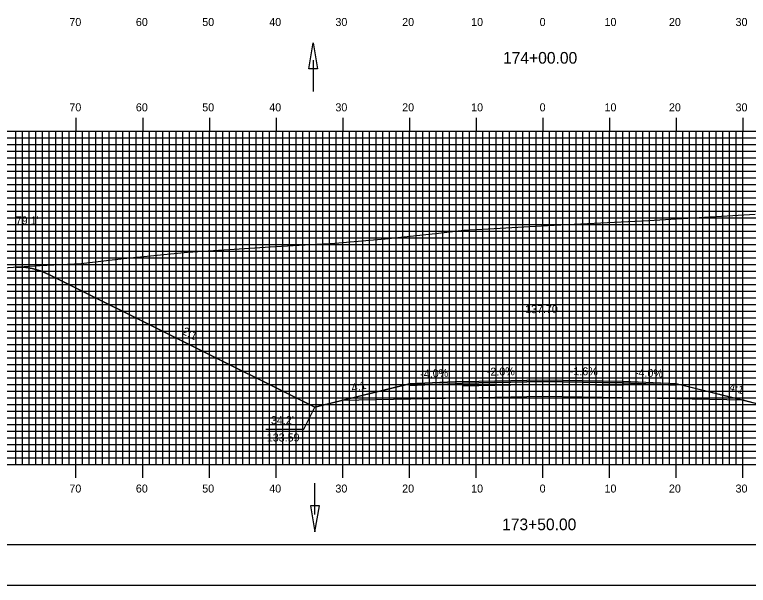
# Model space of a CAD drawing. Extents: x 1783434 to 1783777, y 442591 to 442811.
# Drawn here: x 1783520.8 to 1783630.8, y 442590.5 to 442676.2 of the extents above; entities that cross this region are included whole.
import ezdxf

# ---------------------------------------------------------------- set-up
doc = ezdxf.new("R2010")
doc.units = 0
for name, color, linetype in [('ANNOTATION', 7, 'Continuous'), ('BORDER', 7, 'Continuous'), ('D_Drainage_Ditch_Line', 7, 'Continuous'), ('D_Roadway_Centerline', 7, 'Continuous'), ('D_Roadway_Centerline_Text', 7, 'Continuous'), ('D_Roadway_Edge_Shoulder', 7, 'Continuous'), ('D_Roadway_Edge_TW', 7, 'Continuous'), ('D_Roadway_Pavement', 7, 'Continuous'), ('D_Roadway_SlopeLines', 7, 'Continuous'), ('D_Roadway_SubGrade', 7, 'Continuous'), ('D_Text_Standard', 7, 'Continuous'), ('H_V ANNOTATION', 7, 'Continuous'), ('MAJOR', 7, 'Continuous'), ('MINOR', 7, 'Continuous'), ('PLOT BOUNDARY', 7, 'Continuous'), ('S_Roadway_Centerline', 7, 'Continuous')]:
    doc.layers.add(name, color=color, linetype=linetype)

msp = doc.modelspace()

# ---------------------------------------------------------------- linework, layer by layer
at = {"layer": 'ANNOTATION'}
msp.add_lwpolyline([(1783558.46, 442614), (1783564.15, 442614), (1783565.8, 442617.26)], dxfattribs=at)
at = {"layer": 'BORDER'}
msp.add_lwpolyline([(1783450.37, 442596.67), (1783770.37, 442596.67), (1783770.37, 442806.67), (1783450.37, 442806.67)], close=True, dxfattribs=at)
at = {"layer": 'D_Drainage_Ditch_Line'}
for p, q in [((1783565.54, 442669.34), (1783565.54, 442664.64)), ((1783565.8, 442601.18), (1783565.8, 442605.88))]:
    msp.add_line(p, q, dxfattribs=at)
for points in [[(1783566.2, 442668.03), (1783564.88, 442668.03), (1783565.54, 442671.96)], [(1783566.46, 442602.49), (1783565.14, 442602.49), (1783565.8, 442598.56)]]:
    msp.add_lwpolyline(points, close=True, dxfattribs=at)
at = {"layer": 'D_Roadway_Centerline'}
msp.add_lwpolyline([(1783520.91, 442638.3), (1783522.16, 442638.29), (1783523.41, 442638.1), (1783524.66, 442637.74), (1783525.91, 442637.2), (1783565.8, 442617.26), (1783569.8, 442618.26), (1783579.97, 442620.8), (1783587.97, 442621.12), (1783599.97, 442621.36), (1783611.97, 442621.17), (1783619.97, 442620.85), (1783630.15, 442618.31), (1783636.61, 442616.7), (1783701.63, 442649.21), (1783702.88, 442649.76), (1783704.13, 442650.18), (1783705.38, 442650.47), (1783706.63, 442650.62)], dxfattribs=at)
at = {"layer": 'D_Roadway_Edge_Shoulder'}
for points in [[(1783587.97, 442621.12), (1783579.97, 442620.8), (1783579.97, 442620.55), (1783587.97, 442620.87)], [(1783611.97, 442621.17), (1783619.97, 442620.85), (1783619.97, 442620.6), (1783611.97, 442620.92)]]:
    msp.add_lwpolyline(points, close=True, dxfattribs=at)
at = {"layer": 'D_Roadway_Edge_TW'}
msp.add_lwpolyline([(1783587.97, 442620.87), (1783587.97, 442621.12), (1783599.97, 442621.36), (1783611.97, 442621.17), (1783611.97, 442620.92), (1783599.97, 442621.11)], close=True, dxfattribs=at)
at = {"layer": 'D_Roadway_Pavement'}
msp.add_lwpolyline([(1783587.97, 442620.45), (1783587.97, 442620.87), (1783599.97, 442621.11), (1783611.97, 442620.92), (1783611.97, 442620.51), (1783599.97, 442620.69)], close=True, dxfattribs=at)
at = {"layer": 'D_Roadway_SlopeLines'}
for points in [[(1783565.8, 442617.26), (1783525.91, 442637.2), (1783524.66, 442637.74), (1783523.41, 442638.1), (1783522.16, 442638.29), (1783520.91, 442638.3)], [(1783579.97, 442620.8), (1783565.8, 442617.26)], [(1783619.97, 442620.85), (1783636.61, 442616.7)]]:
    msp.add_lwpolyline(points, dxfattribs=at)
at = {"layer": 'D_Roadway_SubGrade'}
msp.add_lwpolyline([(1783587.97, 442618.62), (1783569.8, 442618.26), (1783579.97, 442620.8), (1783579.97, 442620.55), (1783587.97, 442620.87), (1783599.97, 442621.11), (1783611.97, 442620.92), (1783619.97, 442620.6), (1783619.97, 442620.85), (1783630.15, 442618.31), (1783611.97, 442618.67), (1783599.97, 442618.86)], close=True, dxfattribs=at)
at = {"layer": 'MAJOR'}
for p, q in [((1783529.97, 442660.67), (1783529.97, 442658.67)), ((1783539.97, 442660.67), (1783539.97, 442658.67)), ((1783549.97, 442660.67), (1783549.97, 442658.67)), ((1783559.97, 442660.67), (1783559.97, 442658.67)), ((1783569.97, 442660.67), (1783569.97, 442658.67)), ((1783579.97, 442660.67), (1783579.97, 442658.67)), ((1783589.97, 442660.67), (1783589.97, 442658.67)), ((1783599.97, 442660.67), (1783599.97, 442658.67)), ((1783609.97, 442660.67), (1783609.97, 442658.67)), ((1783619.97, 442660.67), (1783619.97, 442658.67)), ((1783629.97, 442660.67), (1783629.97, 442658.67)), ((1783459.97, 442658.67), (1783739.97, 442658.67)), ((1783459.97, 442658.67), (1783739.97, 442658.67)), ((1783529.97, 442608.67), (1783529.97, 442658.67)), ((1783539.97, 442608.67), (1783539.97, 442658.67)), ((1783549.97, 442608.67), (1783549.97, 442658.67)), ((1783559.97, 442608.67), (1783559.97, 442658.67)), ((1783569.97, 442608.67), (1783569.97, 442658.67)), ((1783579.97, 442608.67), (1783579.97, 442658.67)), ((1783589.97, 442608.67), (1783589.97, 442658.67)), ((1783599.97, 442608.67), (1783599.97, 442658.67)), ((1783609.97, 442608.67), (1783609.97, 442658.67)), ((1783619.97, 442608.67), (1783619.97, 442658.67)), ((1783629.97, 442608.67), (1783629.97, 442658.67)), ((1783459.97, 442653.67), (1783739.97, 442653.67)), ((1783459.97, 442648.67), (1783739.97, 442648.67)), ((1783459.97, 442643.67), (1783739.97, 442643.67)), ((1783459.97, 442638.67), (1783739.97, 442638.67)), ((1783459.97, 442633.67), (1783739.97, 442633.67)), ((1783459.97, 442628.67), (1783739.97, 442628.67)), ((1783459.97, 442623.67), (1783739.97, 442623.67)), ((1783459.97, 442618.67), (1783739.97, 442618.67)), ((1783459.97, 442613.67), (1783739.97, 442613.67)), ((1783459.97, 442608.67), (1783739.97, 442608.67)), ((1783459.97, 442608.67), (1783739.97, 442608.67)), ((1783529.97, 442606.66), (1783529.97, 442608.67)), ((1783539.97, 442606.66), (1783539.97, 442608.67)), ((1783549.97, 442606.66), (1783549.97, 442608.67)), ((1783559.97, 442606.66), (1783559.97, 442608.67)), ((1783569.97, 442606.66), (1783569.97, 442608.67)), ((1783579.97, 442606.66), (1783579.97, 442608.67)), ((1783589.97, 442606.66), (1783589.97, 442608.67)), ((1783599.97, 442606.66), (1783599.97, 442608.67)), ((1783609.97, 442606.66), (1783609.97, 442608.67)), ((1783619.97, 442606.66), (1783619.97, 442608.67)), ((1783629.97, 442606.66), (1783629.97, 442608.67))]:
    msp.add_line(p, q, dxfattribs=at)
at = {"layer": 'MINOR'}
for p, q in [((1783459.97, 442657.67), (1783739.97, 442657.67)), ((1783520.97, 442608.67), (1783520.97, 442658.67)), ((1783521.97, 442608.67), (1783521.97, 442658.67)), ((1783522.97, 442608.67), (1783522.97, 442658.67)), ((1783523.97, 442608.67), (1783523.97, 442658.67)), ((1783524.97, 442608.67), (1783524.97, 442658.67)), ((1783525.97, 442608.67), (1783525.97, 442658.67)), ((1783526.97, 442608.67), (1783526.97, 442658.67)), ((1783527.97, 442608.67), (1783527.97, 442658.67)), ((1783528.97, 442608.67), (1783528.97, 442658.67)), ((1783530.97, 442608.67), (1783530.97, 442658.67)), ((1783531.97, 442608.67), (1783531.97, 442658.67)), ((1783532.97, 442608.67), (1783532.97, 442658.67)), ((1783533.97, 442608.67), (1783533.97, 442658.67)), ((1783534.97, 442608.67), (1783534.97, 442658.67)), ((1783535.97, 442608.67), (1783535.97, 442658.67)), ((1783536.97, 442608.67), (1783536.97, 442658.67)), ((1783537.97, 442608.67), (1783537.97, 442658.67)), ((1783538.97, 442608.67), (1783538.97, 442658.67)), ((1783540.97, 442608.67), (1783540.97, 442658.67)), ((1783541.97, 442608.67), (1783541.97, 442658.67)), ((1783542.97, 442608.67), (1783542.97, 442658.67)), ((1783543.97, 442608.67), (1783543.97, 442658.67)), ((1783544.97, 442608.67), (1783544.97, 442658.67)), ((1783545.97, 442608.67), (1783545.97, 442658.67)), ((1783546.97, 442608.67), (1783546.97, 442658.67)), ((1783547.97, 442608.67), (1783547.97, 442658.67)), ((1783548.97, 442608.67), (1783548.97, 442658.67)), ((1783550.97, 442608.67), (1783550.97, 442658.67)), ((1783551.97, 442608.67), (1783551.97, 442658.67)), ((1783552.97, 442608.67), (1783552.97, 442658.67)), ((1783553.97, 442608.67), (1783553.97, 442658.67)), ((1783554.97, 442608.67), (1783554.97, 442658.67)), ((1783555.97, 442608.67), (1783555.97, 442658.67)), ((1783556.97, 442608.67), (1783556.97, 442658.67)), ((1783557.97, 442608.67), (1783557.97, 442658.67)), ((1783558.97, 442608.67), (1783558.97, 442658.67)), ((1783560.97, 442608.67), (1783560.97, 442658.67)), ((1783561.97, 442608.67), (1783561.97, 442658.67)), ((1783562.97, 442608.67), (1783562.97, 442658.67)), ((1783563.97, 442608.67), (1783563.97, 442658.67)), ((1783564.97, 442608.67), (1783564.97, 442658.67)), ((1783565.97, 442608.67), (1783565.97, 442658.67)), ((1783566.97, 442608.67), (1783566.97, 442658.67)), ((1783567.97, 442608.67), (1783567.97, 442658.67)), ((1783568.97, 442608.67), (1783568.97, 442658.67)), ((1783570.97, 442608.67), (1783570.97, 442658.67)), ((1783571.97, 442608.67), (1783571.97, 442658.67)), ((1783572.97, 442608.67), (1783572.97, 442658.67)), ((1783573.97, 442608.67), (1783573.97, 442658.67)), ((1783574.97, 442608.67), (1783574.97, 442658.67)), ((1783575.97, 442608.67), (1783575.97, 442658.67)), ((1783576.97, 442608.67), (1783576.97, 442658.67)), ((1783577.97, 442608.67), (1783577.97, 442658.67)), ((1783578.97, 442608.67), (1783578.97, 442658.67)), ((1783580.97, 442608.67), (1783580.97, 442658.67)), ((1783581.97, 442608.67), (1783581.97, 442658.67)), ((1783582.97, 442608.67), (1783582.97, 442658.67)), ((1783583.97, 442608.67), (1783583.97, 442658.67)), ((1783584.97, 442608.67), (1783584.97, 442658.67)), ((1783585.97, 442608.67), (1783585.97, 442658.67)), ((1783586.97, 442608.67), (1783586.97, 442658.67)), ((1783587.97, 442608.67), (1783587.97, 442658.67)), ((1783588.97, 442608.67), (1783588.97, 442658.67)), ((1783590.97, 442608.67), (1783590.97, 442658.67)), ((1783591.97, 442608.67), (1783591.97, 442658.67)), ((1783592.97, 442608.67), (1783592.97, 442658.67)), ((1783593.97, 442608.67), (1783593.97, 442658.67)), ((1783594.97, 442608.67), (1783594.97, 442658.67)), ((1783595.97, 442608.67), (1783595.97, 442658.67)), ((1783596.97, 442608.67), (1783596.97, 442658.67)), ((1783597.97, 442608.67), (1783597.97, 442658.67)), ((1783598.97, 442608.67), (1783598.97, 442658.67)), ((1783600.97, 442608.67), (1783600.97, 442658.67)), ((1783601.97, 442608.67), (1783601.97, 442658.67)), ((1783602.97, 442608.67), (1783602.97, 442658.67)), ((1783603.97, 442608.67), (1783603.97, 442658.67)), ((1783604.97, 442608.67), (1783604.97, 442658.67)), ((1783605.97, 442608.67), (1783605.97, 442658.67)), ((1783606.97, 442608.67), (1783606.97, 442658.67)), ((1783607.97, 442608.67), (1783607.97, 442658.67)), ((1783608.97, 442608.67), (1783608.97, 442658.67)), ((1783610.97, 442608.67), (1783610.97, 442658.67)), ((1783611.97, 442608.67), (1783611.97, 442658.67)), ((1783612.97, 442608.67), (1783612.97, 442658.67)), ((1783613.97, 442608.67), (1783613.97, 442658.67)), ((1783614.97, 442608.67), (1783614.97, 442658.67)), ((1783615.97, 442608.67), (1783615.97, 442658.67)), ((1783616.97, 442608.67), (1783616.97, 442658.67)), ((1783617.97, 442608.67), (1783617.97, 442658.67)), ((1783618.97, 442608.67), (1783618.97, 442658.67)), ((1783620.97, 442608.67), (1783620.97, 442658.67)), ((1783621.97, 442608.67), (1783621.97, 442658.67)), ((1783622.97, 442608.67), (1783622.97, 442658.67)), ((1783623.97, 442608.67), (1783623.97, 442658.67)), ((1783624.97, 442608.67), (1783624.97, 442658.67)), ((1783625.97, 442608.67), (1783625.97, 442658.67)), ((1783626.97, 442608.67), (1783626.97, 442658.67)), ((1783627.97, 442608.67), (1783627.97, 442658.67)), ((1783628.97, 442608.67), (1783628.97, 442658.67)), ((1783459.97, 442656.67), (1783739.97, 442656.67)), ((1783459.97, 442655.67), (1783739.97, 442655.67)), ((1783459.97, 442654.67), (1783739.97, 442654.67)), ((1783459.97, 442652.67), (1783739.97, 442652.67)), ((1783459.97, 442651.67), (1783739.97, 442651.67)), ((1783459.97, 442650.67), (1783739.97, 442650.67)), ((1783459.97, 442649.67), (1783739.97, 442649.67)), ((1783459.97, 442647.67), (1783739.97, 442647.67)), ((1783459.97, 442646.67), (1783739.97, 442646.67)), ((1783459.97, 442645.67), (1783739.97, 442645.67)), ((1783459.97, 442644.67), (1783739.97, 442644.67)), ((1783459.97, 442642.67), (1783739.97, 442642.67)), ((1783459.97, 442641.67), (1783739.97, 442641.67)), ((1783459.97, 442640.67), (1783739.97, 442640.67)), ((1783459.97, 442639.67), (1783739.97, 442639.67)), ((1783459.97, 442637.67), (1783739.97, 442637.67)), ((1783459.97, 442636.67), (1783739.97, 442636.67)), ((1783459.97, 442635.67), (1783739.97, 442635.67)), ((1783459.97, 442634.67), (1783739.97, 442634.67)), ((1783459.97, 442632.67), (1783739.97, 442632.67)), ((1783459.97, 442631.67), (1783739.97, 442631.67)), ((1783459.97, 442630.67), (1783739.97, 442630.67)), ((1783459.97, 442629.67), (1783739.97, 442629.67)), ((1783459.97, 442627.67), (1783739.97, 442627.67)), ((1783459.97, 442626.67), (1783739.97, 442626.67)), ((1783459.97, 442625.67), (1783739.97, 442625.67)), ((1783459.97, 442624.67), (1783739.97, 442624.67)), ((1783459.97, 442622.67), (1783739.97, 442622.67)), ((1783459.97, 442621.67), (1783739.97, 442621.67)), ((1783459.97, 442620.67), (1783739.97, 442620.67)), ((1783459.97, 442619.67), (1783739.97, 442619.67)), ((1783459.97, 442617.67), (1783739.97, 442617.67)), ((1783459.97, 442616.67), (1783739.97, 442616.67)), ((1783459.97, 442615.67), (1783739.97, 442615.67)), ((1783459.97, 442614.67), (1783739.97, 442614.67)), ((1783459.97, 442612.67), (1783739.97, 442612.67)), ((1783459.97, 442611.67), (1783739.97, 442611.67)), ((1783459.97, 442610.67), (1783739.97, 442610.67)), ((1783459.97, 442609.67), (1783739.97, 442609.67))]:
    msp.add_line(p, q, dxfattribs=at)
at = {"layer": 'PLOT BOUNDARY'}
msp.add_lwpolyline([(1783434.19, 442590.55), (1783774.19, 442590.55), (1783774.19, 442810.55), (1783434.19, 442810.55)], close=True, dxfattribs=at)
at = {"layer": 'S_Roadway_Centerline'}
msp.add_lwpolyline([(1783459.97, 442633.68), (1783465.87, 442634.46), (1783471.99, 442634.96), (1783490.78, 442636.41), (1783496.32, 442636.77), (1783501.38, 442637.03), (1783513.22, 442637.72), (1783518.13, 442638.13), (1783524.59, 442638.53), (1783530.76, 442638.85), (1783537.11, 442639.57), (1783546.69, 442640.56), (1783559.88, 442641.38), (1783568.8, 442641.88), (1783576.31, 442642.56), (1783584.33, 442643.37), (1783588.11, 442643.84), (1783591.77, 442644.06), (1783600.65, 442644.52), (1783608.68, 442644.95), (1783615.82, 442645.3), (1783631.83, 442646.26)], dxfattribs=at)

# ---------------------------------------------------------------- texts
at = {"layer": 'ANNOTATION'}
for s, rotation, p in [('2:1', 333.4349, (1783545.79, 442628.3)), ('-4.0%', 2.2906, (1783581.61, 442621.67)), ('-2.0%', 1.1458, (1783591.58, 442621.99)), ('-1.6%', 359.1022, (1783604.01, 442622.1)), ('-4.0%', 357.7094, (1783613.76, 442621.9)), ('4:1', 14.0362, (1783571.42, 442619.53)), ('4:1', 345.9638, (1783627.8, 442619.76))]:
    msp.add_text(s, height=1.2, rotation=rotation, dxfattribs=at).set_placement(p)
for s, p in [("34.2'", (1783559.2, 442614.73)), ('133.59', (1783558.58, 442612.13))]:
    msp.add_text(s, height=1.2, dxfattribs=at).set_placement(p)
at = {"layer": 'D_Roadway_Centerline'}
for s, p in [('C', (1783599.97, 442621.36)), ('L', (1783599.97, 442621.35))]:
    msp.add_text(s, height=0.0146, dxfattribs=at).set_placement(p)
at = {"layer": 'D_Roadway_Centerline_Text'}
msp.add_text('137.70', height=1.2, dxfattribs=at).set_placement((1783597.31, 442631.39))
at = {"layer": 'D_Text_Standard'}
msp.add_text("79.1'", height=1.2, dxfattribs=at).set_placement((1783520.94, 442644.7))
at = {"layer": 'H_V ANNOTATION'}
for s, height, p in [('70', 1.2, (1783528.98, 442674.47)), ('60', 1.2, (1783538.95, 442674.47)), ('50', 1.2, (1783548.9, 442674.47)), ('40', 1.2, (1783558.95, 442674.47)), ('30', 1.2, (1783568.87, 442674.47)), ('20', 1.2, (1783578.88, 442674.47)), ('10', 1.2, (1783589.22, 442674.47)), ('0', 1.2, (1783599.49, 442674.47)), ('10', 1.2, (1783609.22, 442674.47)), ('20', 1.2, (1783618.88, 442674.47)), ('30', 1.2, (1783628.87, 442674.47)), ('174+00.00', 1.75, (1783594, 442668.82)), ('70', 1.2, (1783528.98, 442661.67)), ('60', 1.2, (1783538.95, 442661.67)), ('50', 1.2, (1783548.9, 442661.67)), ('40', 1.2, (1783558.95, 442661.67)), ('30', 1.2, (1783568.87, 442661.67)), ('20', 1.2, (1783578.88, 442661.67)), ('10', 1.2, (1783589.22, 442661.67)), ('0', 1.2, (1783599.49, 442661.67)), ('10', 1.2, (1783609.22, 442661.67)), ('20', 1.2, (1783618.88, 442661.67)), ('30', 1.2, (1783628.87, 442661.67)), ('70', 1.2, (1783528.98, 442604.47)), ('60', 1.2, (1783538.95, 442604.47)), ('50', 1.2, (1783548.9, 442604.47)), ('40', 1.2, (1783558.95, 442604.47)), ('30', 1.2, (1783568.87, 442604.47)), ('20', 1.2, (1783578.88, 442604.47)), ('10', 1.2, (1783589.22, 442604.47)), ('0', 1.2, (1783599.49, 442604.47)), ('10', 1.2, (1783609.22, 442604.47)), ('20', 1.2, (1783618.88, 442604.47)), ('30', 1.2, (1783628.87, 442604.47)), ('173+50.00', 1.75, (1783593.86, 442598.82))]:
    msp.add_text(s, height=height, dxfattribs=at).set_placement(p)

doc.saveas('drawing.dxf')
